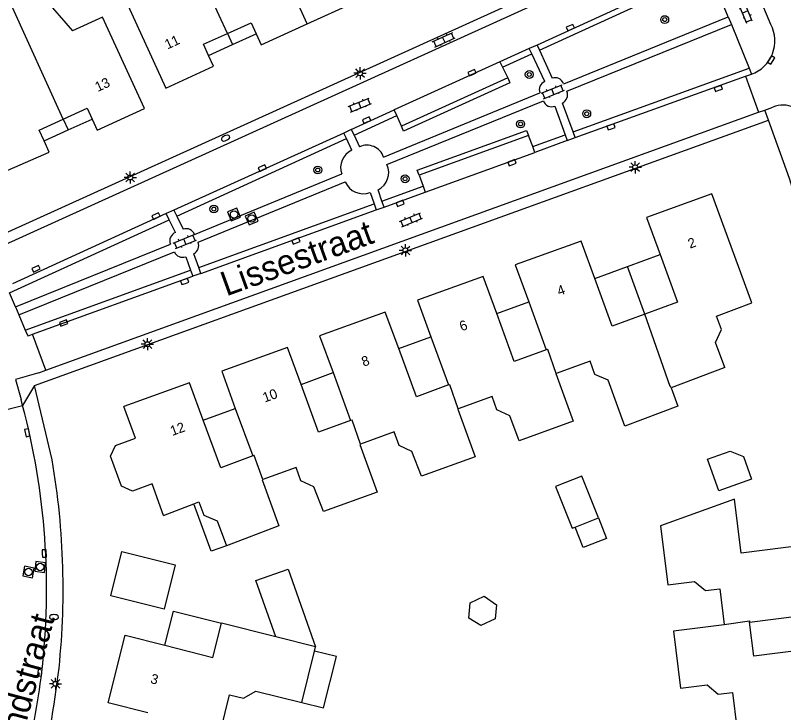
# Model space of a CAD drawing. Extents: x 128000 to 131008, y 398996 to 402500.
# Drawn here: x 128168.1 to 128246.4, y 399767.2 to 399838.2 of the extents above; entities that cross this region are included whole.
import ezdxf

# ---------------------------------------------------------------- set-up
doc = ezdxf.new("R2010")
doc.units = 0
for name, color, linetype in [('gg-anno-huisnummerreeks BGT', 7, 'Continuous'), ('gg-anno-openbare ruimte label', 7, 'Continuous'), ('gg-bbg-gedigitaliseerde bebouwing', 7, 'Continuous'), ('gg-bbg-gedigitaliseerde bijgebouw', 7, 'Continuous'), ('gg-bbg-hoofdgebouw', 7, 'Continuous'), ('gg-bbg-luifel en loopbrug', 7, 'Continuous'), ('gg-bbg-tussenscheiding', 7, 'Continuous'), ('gg-knt-verharding', 7, 'Continuous'), ('gg-knt-verharding nz', 7, 'Continuous'), ('gt-grn-groengrens', 7, 'Continuous'), ('gt-grn-vlakafsluiter', 7, 'Continuous'), ('gt-grn-weggrens', 7, 'Continuous'), ('gt-symb-boom', 7, 'Continuous'), ('gt-symb-brandkraan', 7, 'Continuous'), ('gt-symb-klinker verharding', 7, 'Continuous'), ('gt-symb-kolk', 7, 'Continuous'), ('gt-symb-lichtmast', 7, 'Continuous'), ('gt-symb-rioolschacht', 7, 'Continuous')]:
    doc.layers.add(name, color=color, linetype=linetype)

# ---------------------------------------------------------------- blocks, each defined once
blk = doc.blocks.new('gt0-KL1')
at = {"layer": 'gt-symb-klinker verharding'}
for p, q in [((-1.15, 0.3), (1.15, 0.3)), ((-1, -0.3), (-1, 0.3)), ((-0.5, 0.3), (-0.5, 0.45)), ((0, -0.3), (0, 0.3)), ((0.5, 0.3), (0.5, 0.45)), ((1, -0.3), (1, 0.3)), ((-1.15, -0.3), (1.15, -0.3)), ((-0.5, -0.45), (-0.5, -0.3)), ((0.5, -0.45), (0.5, -0.3))]:
    blk.add_line(p, q, dxfattribs=at)
blk = doc.blocks.new('gt0-BOOM')
at = {"layer": 'gt-symb-boom'}
for radius in [0.4, 0.2]:
    blk.add_circle((0, 0), radius, dxfattribs=at)
blk = doc.blocks.new('gt0-KOLK')
at = {"layer": 'gt-symb-kolk'}
blk.add_lwpolyline([(0, 0), (0.375, 0), (0.375, 0.4), (-0.375, 0.4), (-0.375, 0), (0, 0)], dxfattribs=at)
blk = doc.blocks.new('gt0-LMAST')
at = {"layer": 'gt-symb-lichtmast'}
for p, q in [((-0.182, 0.173), (-0.447, 0.438)), ((-0.005, 0.246), (-0.005, 0.621)), ((0.172, 0.173), (0.437, 0.438)), ((-0.255, -0.004), (-0.63, -0.004)), ((-0.182, -0.181), (-0.447, -0.446)), ((-0.005, -0.254), (-0.005, -0.629)), ((0.437, -0.446), (0.172, -0.181)), ((0.245, -0.004), (0.62, -0.004))]:
    blk.add_line(p, q, dxfattribs=at)
blk.add_circle((-0.005, -0.004), 0.25, dxfattribs=at)
blk = doc.blocks.new('gt0-BR')
at = {"layer": 'gt-symb-brandkraan'}
for centre, radius, start, end in [((-0.244, 0), 0.206, 107.56694, 252.43307), ((0.599, -2.664), 3, 106.89205, 107.56694), ((0, -0.691), 0.938, 73.10799, 106.89205), ((-0.599, -2.664), 3, 72.43309, 73.10799), ((0.244, 0), 0.206, 287.56695, 72.43309), ((0.599, 2.664), 3, 252.43307, 253.10797), ((0, 0.691), 0.938, 253.10797, 286.89206), ((-0.599, 2.664), 3, 286.89206, 287.56695)]:
    blk.add_arc(centre, radius, start, end, dxfattribs=at)
blk = doc.blocks.new('gt0-RS')
at = {"layer": 'gt-symb-rioolschacht'}
blk.add_lwpolyline([(-0.5, -0.5), (0.5, -0.5), (0.5, 0.5), (-0.5, 0.5)], close=True, dxfattribs=at)
blk.add_circle((0, 0), 0.375, dxfattribs=at)

msp = doc.modelspace()

# ---------------------------------------------------------------- linework, layer by layer
at = {"layer": 'gg-bbg-gedigitaliseerde bebouwing'}
for p, q in [((128170.5, 399840.626), (128173.969, 399836.601)), ((128240.384, 399802.326), (128234.921, 399800.245)), ((128234.921, 399800.245), (128235.594, 399798.372)), ((128235.594, 399798.372), (128230.209, 399796.32)), ((128194.665, 399774.881), (128189.144, 399776.275)), ((128198.605, 399773.419), (128198.714, 399773.859)), ((128197.306, 399768.188), (128198.605, 399773.419))]:
    msp.add_line(p, q, dxfattribs=at)
for points in [[(128230.209, 399796.32), (128228.494, 399801.023), (128227.161, 399801.597), (128226.668, 399802.96), (128223.225, 399801.714)], [(128223.225, 399801.714), (128223.169, 399801.694), (128224.93, 399796.828), (128219.452, 399794.846), (128218.492, 399797.37), (128217.178, 399797.984), (128216.685, 399799.347), (128213.242, 399798.101)], [(128213.242, 399798.101), (128213.186, 399798.081), (128214.946, 399793.216), (128209.487, 399791.24), (128208.527, 399793.764), (128207.213, 399794.378), (128206.72, 399795.741), (128203.277, 399794.495)], [(128203.277, 399794.495), (128203.221, 399794.475), (128204.982, 399789.609), (128199.504, 399787.627), (128198.544, 399790.151), (128197.225, 399790.78), (128196.737, 399792.128), (128193.331, 399790.896)], [(128193.331, 399790.896), (128193.275, 399790.876), (128194.969, 399786.178), (128189.65, 399784.151)], [(128241.351, 399788.914), (128233.832, 399786.197), (128234.561, 399780.174), (128237.277, 399780.499), (128238.417, 399779.582), (128239.856, 399779.759), (128240.302, 399776.139)], [(128240.302, 399776.139), (128240.308, 399776.089), (128235.149, 399775.453), (128235.864, 399769.65), (128238.573, 399769.983), (128239.716, 399769.037), (128241.155, 399769.214), (128241.597, 399765.623)], [(128189.052, 399765.378), (128189.96, 399768.973), (128191.384, 399768.613), (128192.643, 399769.347), (128197.306, 399768.188)]]:
    msp.add_lwpolyline(points, dxfattribs=at)
at = {"layer": 'gg-bbg-gedigitaliseerde bijgebouw'}
msp.add_line((128225.146, 399786.057), (128227.51, 399786.986), dxfattribs=at)
for points in [[(128239.778, 399789.757), (128238.624, 399792.983), (128240.92, 399793.804), (128242.291, 399793.232), (128243.108, 399790.948), (128239.778, 399789.757)], [(128227.51, 399786.986), (128228.332, 399784.893), (128225.968, 399783.965), (128225.146, 399786.057)], [(128194.665, 399774.881), (128192.633, 399780.619), (128195.909, 399781.779), (128198.714, 399773.859)], [(128214.438, 399778.333), (128215.874, 399779.027), (128217.14, 399778.149), (128216.986, 399776.723), (128215.551, 399776.03), (128214.331, 399776.792), (128214.438, 399778.333)]]:
    msp.add_lwpolyline(points, dxfattribs=at)
at = {"layer": 'gg-bbg-hoofdgebouw'}
for p, q in [((128220.42, 399808.997), (128222.199, 399804.124)), ((128210.457, 399805.425), (128212.243, 399800.533)), ((128200.499, 399801.787), (128202.277, 399796.916)), ((128190.543, 399798.15), (128192.314, 399793.299)), ((128183.233, 399787.241), (128186.334, 399788.433)), ((128242.898, 399776.357), (128247.979, 399777.002))]:
    msp.add_line(p, q, dxfattribs=at)
for points in [[(128182.35, 399841.558), (128179.213, 399840.066), (128183.468, 399830.763), (128188.316, 399833.002), (128187.82, 399834.087)], [(128197.85, 399837.303), (128202.516, 399839.413), (128202.019, 399840.5)], [(128175.951, 399827.621), (128176.469, 399826.489), (128181.288, 399828.693), (128177.033, 399837.996), (128173.969, 399836.601)], [(128189.734, 399836.327), (128192.164, 399837.42), (128192.673, 399836.307)], [(128192.673, 399836.307), (128193.183, 399835.192), (128197.85, 399837.303)], [(128187.82, 399834.087), (128187.297, 399835.23), (128189.734, 399836.327)], [(128173.031, 399827.609), (128175.45, 399828.717), (128175.951, 399827.621)], [(128171.083, 399825.393), (128170.583, 399826.487), (128173.031, 399827.609)], [(128165.796, 399824.327), (128166.784, 399822.14), (128171.602, 399824.259), (128171.083, 399825.393)], [(128240.384, 399802.326), (128239.417, 399804.863), (128240.037, 399806.18), (128239.522, 399807.545), (128243.118, 399808.902), (128239.073, 399820.013), (128232.415, 399817.582), (128233.793, 399813.808)], [(128227.13, 399811.374), (128225.741, 399815.178), (128219.047, 399812.757), (128220.42, 399808.997)], [(128233.793, 399813.808), (128235.567, 399808.949), (128232.223, 399807.739)], [(128217.155, 399807.804), (128215.781, 399811.564), (128209.091, 399809.166), (128210.457, 399805.425)], [(128232.223, 399807.739), (128228.896, 399806.536), (128227.13, 399811.374)], [(128207.183, 399804.229), (128205.813, 399807.957), (128199.125, 399805.549), (128200.499, 399801.787)], [(128222.199, 399804.124), (128218.938, 399802.922), (128217.155, 399807.804)], [(128197.233, 399800.594), (128195.856, 399804.363), (128189.162, 399801.932), (128190.543, 399798.15)], [(128212.243, 399800.533), (128208.982, 399799.331), (128207.183, 399804.229)], [(128187.277, 399796.957), (128185.889, 399800.758), (128179.193, 399798.328)], [(128202.277, 399796.916), (128199.016, 399795.714), (128197.233, 399800.594)], [(128183.233, 399787.241), (128182.066, 399790.445), (128180.064, 399789.716), (128178.959, 399790.207), (128177.836, 399793.289), (128178.353, 399794.382), (128180.364, 399795.115), (128179.193, 399798.328)], [(128192.314, 399793.299), (128189.053, 399792.097), (128187.277, 399796.957)], [(128186.334, 399788.433), (128186.821, 399788.62), (128187.344, 399787.259), (128188.683, 399786.688), (128189.65, 399784.151)], [(128247.979, 399777.002), (128252.025, 399777.515), (128251.149, 399784.55), (128242.032, 399783.393), (128241.351, 399788.914)], [(128183.377, 399774.024), (128188.259, 399772.786), (128189.144, 399776.275)], [(128248.418, 399773.536), (128243.334, 399772.891), (128242.898, 399776.357)], [(128181.643, 399767.138), (128177.604, 399768.149), (128179.341, 399775.048), (128183.377, 399774.024)]]:
    msp.add_lwpolyline(points, dxfattribs=at)
at = {"layer": 'gg-bbg-luifel en loopbrug'}
for p, q in [((128189.734, 399836.327), (128190.246, 399835.197)), ((128190.246, 399835.197), (128192.673, 399836.307)), ((128187.82, 399834.087), (128190.246, 399835.197)), ((128173.031, 399827.609), (128173.517, 399826.507)), ((128173.517, 399826.507), (128175.951, 399827.621)), ((128171.083, 399825.393), (128173.517, 399826.507)), ((128230.461, 399812.591), (128233.793, 399813.808)), ((128227.13, 399811.374), (128230.461, 399812.591)), ((128232.223, 399807.739), (128230.461, 399812.591)), ((128217.155, 399807.804), (128220.42, 399808.997)), ((128207.183, 399804.229), (128210.457, 399805.425)), ((128197.233, 399800.594), (128200.499, 399801.787)), ((128187.277, 399796.957), (128190.543, 399798.15))]:
    msp.add_line(p, q, dxfattribs=at)
for points in [[(128227.51, 399786.986), (128225.836, 399791.246), (128223.15, 399790.191), (128224.824, 399785.931), (128225.146, 399786.057)], [(128189.65, 399784.151), (128188.094, 399783.586), (128186.334, 399788.433)], [(128177.868, 399779.061), (128178.988, 399783.553), (128184.425, 399782.196), (128183.304, 399777.705), (128177.868, 399779.061)], [(128183.377, 399774.024), (128184.254, 399777.506), (128189.144, 399776.275)], [(128197.306, 399768.188), (128199.511, 399767.633), (128200.827, 399772.86), (128198.605, 399773.419)]]:
    msp.add_lwpolyline(points, dxfattribs=at)
at = {"layer": 'gg-bbg-tussenscheiding'}
for p, q in [((128189.734, 399836.327), (128184.377, 399848.036)), ((128197.85, 399837.303), (128193.626, 399846.652)), ((128173.031, 399827.609), (128167.7, 399839.356)), ((128198.714, 399773.859), (128194.665, 399774.881))]:
    msp.add_line(p, q, dxfattribs=at)
for points in [[(128234.921, 399800.245), (128234.864, 399800.402), (128234.808, 399800.382), (128232.223, 399807.739)], [(128223.225, 399801.714), (128222.355, 399804.152), (128222.199, 399804.124)], [(128213.242, 399798.101), (128212.39, 399800.548), (128212.24, 399800.494), (128212.243, 399800.533)], [(128203.277, 399794.495), (128202.424, 399796.944), (128202.277, 399796.916)], [(128193.331, 399790.896), (128192.457, 399793.341), (128192.314, 399793.299)], [(128240.302, 399776.139), (128242.885, 399776.495), (128242.898, 399776.357)]]:
    msp.add_lwpolyline(points, dxfattribs=at)
at = {"layer": 'gg-knt-verharding'}
for p, q in [((128236.465, 399846.307), (128166.057, 399814.344)), ((128238.031, 399842.811), (128221.27, 399835.157)), ((128240.726, 399838.032), (128238.821, 399842.563)), ((128245.06, 399837.258), (128243.565, 399840.809)), ((128240.726, 399838.032), (128241.046, 399837.259)), ((128224.298, 399830.44), (128241.046, 399837.259)), ((128241.046, 399837.259), (128242.85, 399832.787)), ((128220.476, 399834.795), (128217.472, 399833.429)), ((128221.27, 399835.157), (128220.476, 399834.795)), ((128220.722, 399834.271), (128220.476, 399834.795)), ((128221.27, 399835.157), (128221.509, 399834.632)), ((128222.054, 399831.427), (128220.722, 399834.271)), ((128221.509, 399834.632), (128222.817, 399831.764)), ((128217.472, 399833.429), (128217.733, 399832.901)), ((128217.733, 399832.901), (128218.271, 399831.811)), ((128242.85, 399832.787), (128243.094, 399832.184)), ((128218.271, 399831.811), (128207.446, 399826.897)), ((128225.142, 399825.727), (128242.5, 399831.97)), ((128242.5, 399831.97), (128243.094, 399832.184)), ((128242.5, 399831.97), (128243.815, 399828.309)), ((128205.643, 399823.74), (128221.551, 399830.271)), ((128205.982, 399822.976), (128221.903, 399829.46)), ((128224.93, 399826.304), (128223.851, 399829.246)), ((128202.346, 399826.56), (128206.719, 399828.544)), ((128206.972, 399827.971), (128206.719, 399828.544)), ((128223.085, 399828.941), (128224.122, 399826.011)), ((128243.815, 399828.309), (128244.443, 399828.536)), ((128244.443, 399828.536), (128245.273, 399828.837)), ((128171.259, 399802.031), (128243.815, 399828.309)), ((128207.446, 399826.897), (128206.972, 399827.971)), ((128170.105, 399800.482), (128244.826, 399827.505)), ((128201.598, 399826.188), (128184.295, 399818.341)), ((128202.346, 399826.56), (128201.598, 399826.188)), ((128201.854, 399825.627), (128201.598, 399826.188)), ((128202.346, 399826.56), (128202.626, 399825.98)), ((128225.142, 399825.727), (128224.93, 399826.304)), ((128202.396, 399824.438), (128201.854, 399825.627)), ((128202.626, 399825.98), (128203.196, 399824.801)), ((128220.39, 399825.932), (128209.248, 399821.886)), ((128220.819, 399824.816), (128220.39, 399825.932)), ((128224.33, 399825.422), (128221.051, 399824.211)), ((128224.122, 399826.011), (128224.33, 399825.422)), ((128224.33, 399825.422), (128225.142, 399825.727)), ((128221.051, 399824.211), (128220.819, 399824.816)), ((128186.391, 399815.87), (128201.375, 399822.025)), ((128209.248, 399821.886), (128209.658, 399820.778)), ((128186.76, 399815.092), (128201.735, 399821.223)), ((128209.658, 399820.778), (128209.887, 399820.159)), ((128204.266, 399820.144), (128204.675, 399818.975)), ((128205.472, 399819.263), (128205.077, 399820.42)), ((128205.68, 399818.653), (128209.887, 399820.159)), ((128205.68, 399818.653), (128205.472, 399819.263)), ((128184.295, 399818.341), (128183.498, 399817.987)), ((128184.295, 399818.341), (128184.598, 399817.721)), ((128187.038, 399811.885), (128204.887, 399818.37)), ((128204.675, 399818.975), (128204.887, 399818.37)), ((128204.887, 399818.37), (128205.68, 399818.653)), ((128183.498, 399817.987), (128167.868, 399810.826)), ((128183.808, 399817.359), (128183.498, 399817.987)), ((128184.598, 399817.721), (128185.243, 399816.403)), ((128184.45, 399816.056), (128183.808, 399817.359)), ((128168.166, 399808.479), (128183.942, 399814.878)), ((128168.508, 399807.66), (128184.341, 399814.095)), ((128185.487, 399813.597), (128185.99, 399812.215)), ((128186.812, 399812.512), (128186.313, 399813.893)), ((128185.99, 399812.215), (128186.213, 399811.603)), ((128187.038, 399811.885), (128186.812, 399812.512)), ((128169.876, 399805.692), (128186.213, 399811.603)), ((128187.038, 399811.885), (128186.213, 399811.603)), ((128168.166, 399808.479), (128167.566, 399809.918)), ((128168.166, 399808.479), (128168.508, 399807.66)), ((128168.508, 399807.66), (128169.149, 399806.121)), ((128169.552, 399805.575), (128169.876, 399805.692)), ((128171.259, 399802.031), (128169.876, 399805.692)), ((128170.542, 399801.771), (128171.259, 399802.031)), ((128171.89, 399792.901), (128170.105, 399800.482)), ((128168.889, 399798.436), (128168.723, 399799.05)), ((128163.982, 399797.195), (128168.889, 399798.436))]:
    msp.add_line(p, q, dxfattribs=at)
for points in [[(128163.914, 399815.957), (128164.475, 399814.788), (128236.661, 399847.582)], [(128223.947, 399831.266), (128223.973, 399831.211), (128240.726, 399838.032)], [(128218.271, 399831.811), (128218.498, 399831.31), (128207.673, 399826.396), (128207.446, 399826.897)], [(128209.248, 399821.886), (128209.06, 399822.403), (128220.202, 399826.449), (128220.39, 399825.932)], [(128169.149, 399806.121), (128169.4, 399805.52), (128169.552, 399805.575)]]:
    msp.add_lwpolyline(points, dxfattribs=at)
for centre, radius, start, end in [((128241.859, 399835.58), 3.614, 289.98125, 27.65949), ((128223.125, 399830.933), 0.887, 22.08514, 110.34792), ((128222.335, 399830.617), 0.857, 109.14085, 203.8294), ((128223.439, 399830.081), 0.931, 296.28312, 22.6679), ((128222.738, 399829.756), 0.886, 199.54619, 293.04257), ((128246.292, 399826.445), 2.6, 16.17544, 113.06498), ((128024.707, 399745.661), 234.842, 13.33851, 20.39599), ((128203.928, 399823.137), 1.818, 19.36882, 113.74883), ((128203.175, 399822.686), 1.917, 113.96659, 200.16456), ((128204.225, 399822.16), 1.938, 296.09723, 24.90783), ((128203.551, 399821.975), 1.966, 202.49755, 291.32402), ((128184.758, 399815.225), 0.887, 110.32607, 203.01871), ((128185.53, 399815.519), 0.929, 22.1797, 108.01076), ((128185.823, 399814.758), 0.994, 299.50115, 19.60687), ((128185.168, 399814.43), 0.892, 202.06477, 290.96004), ((128098.47, 399779.737), 72.859, 353.34873, 14.87112), ((128095.576, 399779.769), 77.436, 353.50789, 9.76347), ((128093.714, 399780.602), 77.684, 345.89199, 353.12165), ((128084.342, 399781.876), 88.839, 345.17683, 352.9769)]:
    msp.add_arc(centre, radius, start, end, dxfattribs=at)
at = {"layer": 'gg-knt-verharding nz'}
for p, q in [((128217.472, 399833.429), (128206.719, 399828.544)), ((128209.887, 399820.159), (128221.051, 399824.211))]:
    msp.add_line(p, q, dxfattribs=at)
at = {"layer": 'gt-grn-groengrens'}
for p, q in [((128221.509, 399834.632), (128238.821, 399842.563)), ((128217.733, 399832.901), (128220.722, 399834.271)), ((128224.93, 399826.304), (128242.85, 399832.787)), ((128202.626, 399825.98), (128206.972, 399827.971)), ((128184.598, 399817.721), (128201.854, 399825.627)), ((128220.819, 399824.816), (128224.122, 399826.011)), ((128205.472, 399819.263), (128209.658, 399820.778)), ((128186.812, 399812.512), (128204.675, 399818.975)), ((128167.566, 399809.918), (128183.808, 399817.359)), ((128169.149, 399806.121), (128185.99, 399812.215))]:
    msp.add_line(p, q, dxfattribs=at)
at = {"layer": 'gt-grn-vlakafsluiter'}
msp.add_lwpolyline([(128170.542, 399801.771), (128168.162, 399801.074), (128168.723, 399799.05)], dxfattribs=at)
at = {"layer": 'gt-grn-weggrens'}
for p, q in [((128244.826, 399827.505), (128244.443, 399828.536)), ((128170.105, 399800.482), (128168.889, 399798.436))]:
    msp.add_line(p, q, dxfattribs=at)

# ---------------------------------------------------------------- block references
at = {"layer": 'gt-symb-boom'}
for p in [(128234.261, 399837.745), (128226.32, 399828.155), (128207.826, 399821.532), (128188.352, 399818.45)]:
    msp.add_blockref('gt0-BOOM', p, dxfattribs=at)
for p, rotation in [((128220.468, 399832.155), -65.53707310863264), ((128219.586, 399827.116), 112.07794163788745), ((128198.939, 399822.43), 90)]:
    msp.add_blockref('gt0-BOOM', p, dxfattribs=dict(at, rotation=rotation))
at = {"layer": 'gt-symb-brandkraan', "rotation": 24.38706671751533}
msp.add_blockref('gt0-BR', (128189.545, 399825.676), dxfattribs=at)
at = {"layer": 'gt-symb-brandkraan'}
msp.add_blockref('gt0-BR', (128172.081, 399776.896), dxfattribs=at)
at = {"layer": 'gt-symb-klinker verharding'}
for p, rotation in [((128242.461, 399838.519), 112.38636556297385), ((128211.771, 399835.691), 24.387066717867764), ((128222.871, 399830.4), 22.15258650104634), ((128203.224, 399829.043), 22.258660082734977), ((128208.437, 399817.347), 22.28037103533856), ((128185.401, 399815.138), 22.280371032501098)]:
    msp.add_blockref('gt0-KL1', p, dxfattribs=dict(at, rotation=rotation))
at = {"layer": 'gt-symb-kolk'}
for p, rotation in [((128224.574, 399837.111), -156.22952418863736), ((128244.923, 399833.73), -121.46487302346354), ((128214.724, 399832.16), 23.95085531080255), ((128239.784, 399830.546), 19.75789996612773), ((128203.981, 399827.326), 24.38706671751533), ((128228.857, 399826.635), 20.247501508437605), ((128218.792, 399822.986), 20.1201657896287), ((128193.37, 399822.436), 24.131125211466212), ((128207.395, 399818.844), 19.68464273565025), ((128182.557, 399817.557), 24.899200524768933), ((128196.776, 399815.011), 20.374899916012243), ((128170.343, 399812.185), 25.155372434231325), ((128185.462, 399810.88), 19.32248237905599), ((128173.127, 399806.654), 20.173944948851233), ((128169.553, 399795.71), 101.65840162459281), ((128170.89, 399783.353), -87.13473427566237), ((128170.445, 399771.276), -96.66296362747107)]:
    msp.add_blockref('gt0-KOLK', p, dxfattribs=dict(at, rotation=rotation))
at = {"layer": 'gt-symb-lichtmast'}
for p in [(128203.246, 399832.278), (128231.265, 399822.709), (128179.847, 399821.669), (128207.862, 399814.244), (128181.595, 399804.689), (128172.241, 399770.094)]:
    msp.add_blockref('gt0-LMAST', p, dxfattribs=at)
at = {"layer": 'gt-symb-rioolschacht'}
for p, rotation in [((128190.411, 399817.901), 22.07794163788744), ((128192.201, 399817.485), 23.898477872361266), ((128170.678, 399781.991), 83.39396584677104), ((128169.479, 399781.481), 79.925667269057)]:
    msp.add_blockref('gt0-RS', p, dxfattribs=dict(at, rotation=rotation))

# ---------------------------------------------------------------- texts
at = {"layer": 'gg-anno-huisnummerreeks BGT'}
for s, rotation, p in [('11', 24.8, (128183.634, 399834.695)), ('13', 24.6, (128176.534, 399830.367)), ('2', 20.1, (128236.837, 399814.405)), ('4', 19.9, (128223.511, 399809.586)), ('6', 19.7, (128213.577, 399805.993)), ('8', 19.8, (128203.606, 399802.38)), ('10', 19.9, (128193.537, 399798.735)), ('12', 19.9, (128184.123, 399795.331)), ('3', 345.9, (128181.838, 399770.175))]:
    msp.add_text(s, height=1, rotation=rotation, dxfattribs=at).set_placement(p)
at = {"layer": 'gg-anno-openbare ruimte label'}
for s, rotation, p in [('Lissestraat', 19.9, (128189.62, 399809.543)), ('Lemsterlandstraat', 74.9, (128165.192, 399750.971))]:
    msp.add_text(s, height=2.5, rotation=rotation, dxfattribs=at).set_placement(p)

doc.saveas('drawing.dxf')
